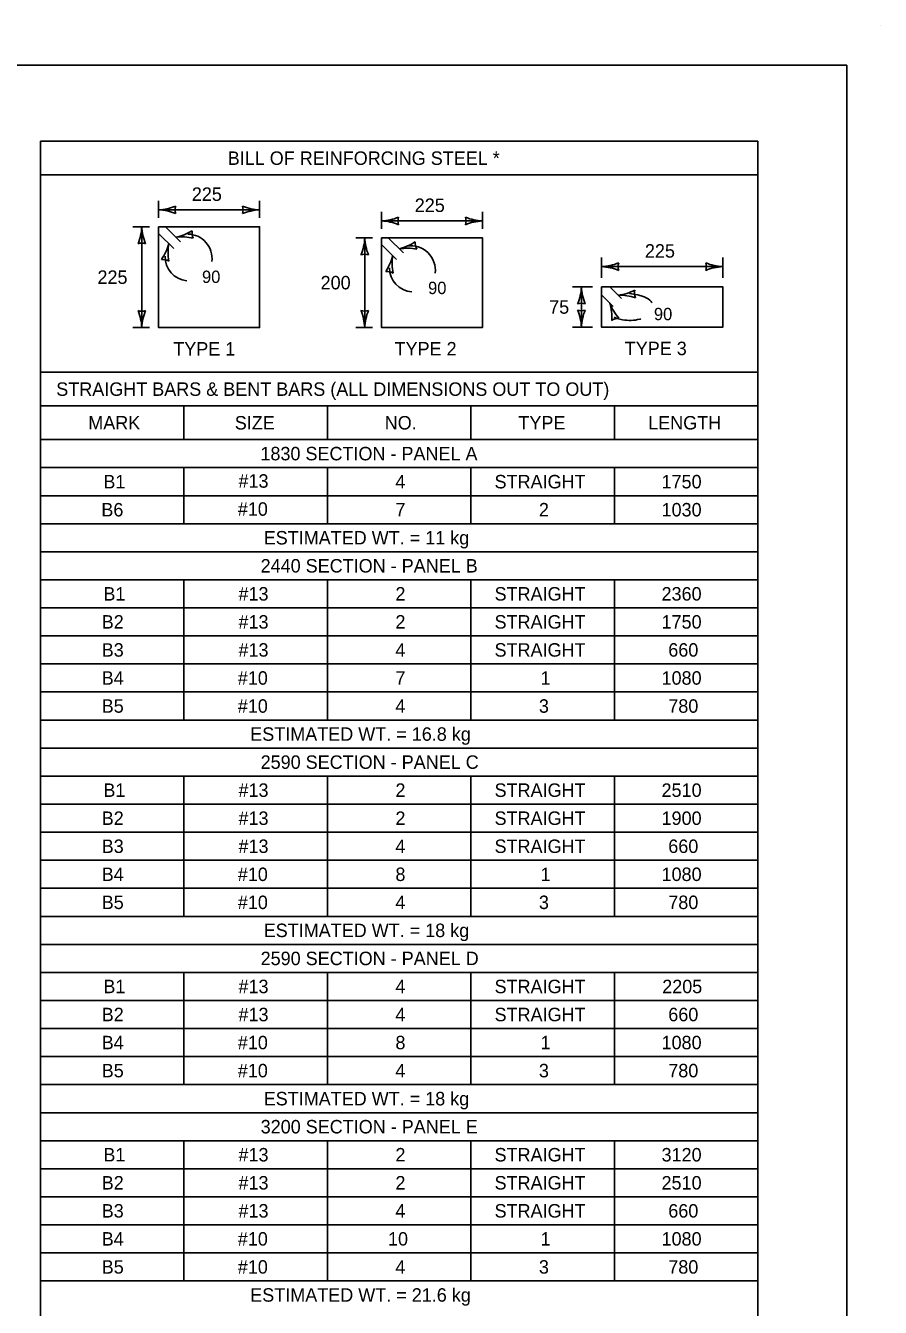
# Model space of a CAD drawing. Extents: x 49991.4 to 50021, y 49987.6 to 50011.4.
# Drawn here: x 50013.09 to 50016.9, y 49993.46 to 49999.18 of the extents above; entities that cross this region are included whole.
import ezdxf

# ---------------------------------------------------------------- set-up
doc = ezdxf.new("R2010")
doc.units = 0
for name, color, linetype in [('Level 1', 7, 'Continuous'), ('Level 2', 7, 'Continuous'), ('Level 3', 7, 'Continuous')]:
    doc.layers.add(name, color=color, linetype=linetype)

msp = doc.modelspace()

# ---------------------------------------------------------------- linework, layer by layer
at = {"layer": 'Level 1'}
for p, q in [((50016.9001, 49999.1756), (50016.9001, 49999.1756)), ((50013.713, 49998.2795), (50013.7802, 49998.2124)), ((50013.683, 49998.2495), (50013.7502, 49998.1824)), ((50014.7066, 49998.23), (50014.7738, 49998.1629)), ((50014.6766, 49998.2), (50014.7438, 49998.1329)), ((50015.6936, 49998.0114), (50015.7458, 49997.9592)), ((50015.6576, 49997.9754), (50015.7098, 49997.9232))]:
    msp.add_line(p, q, dxfattribs=at)
for points in [[(49999.3835, 49998.9992), (50016.7501, 49998.9992), (50016.7501, 49987.7988), (49999.3835, 49987.7988)], [(50013.683, 49998.2795), (50014.133, 49998.2795), (50014.133, 49997.8295), (50013.683, 49997.8295)], [(50014.6766, 49998.23), (50015.1266, 49998.23), (50015.1266, 49997.8299), (50014.6766, 49997.8299)], [(50015.6576, 49998.0114), (50016.1976, 49998.0114), (50016.1976, 49997.8314), (50015.6576, 49997.8314)]]:
    msp.add_lwpolyline(points, close=True, dxfattribs=at)
at = {"layer": 'Level 2'}
for p, q in [((50013.1565, 49998.6599), (50016.3545, 49998.6599)), ((50013.1565, 49991.0805), (50013.1565, 49998.6599)), ((50016.3545, 49991.0805), (50016.3545, 49998.6599)), ((50013.1565, 49998.5099), (50016.3545, 49998.5099)), ((50016.3545, 49997.6305), (50013.1565, 49997.6305)), ((50016.3545, 49997.4805), (50013.1565, 49997.4805)), ((50013.7961, 49997.3305), (50013.7961, 49997.4805)), ((50014.4357, 49997.3305), (50014.4357, 49997.4805)), ((50015.0753, 49997.3305), (50015.0753, 49997.4805)), ((50015.7149, 49997.3305), (50015.7149, 49997.4805)), ((50016.3545, 49997.3305), (50013.1565, 49997.3305)), ((50016.3545, 49997.2055), (50013.1565, 49997.2055)), ((50013.7961, 49996.9555), (50013.7961, 49997.2055)), ((50014.4357, 49996.9555), (50014.4357, 49997.2055)), ((50015.0753, 49996.9555), (50015.0753, 49997.2055)), ((50015.7149, 49996.9555), (50015.7149, 49997.2055)), ((50016.3545, 49997.0805), (50013.1565, 49997.0805)), ((50016.3545, 49996.9555), (50013.1565, 49996.9555)), ((50016.3545, 49996.8305), (50013.1565, 49996.8305)), ((50016.3545, 49996.7055), (50013.1565, 49996.7055)), ((50013.7961, 49996.0805), (50013.7961, 49996.7055)), ((50014.4357, 49996.0805), (50014.4357, 49996.7055)), ((50015.0753, 49996.0805), (50015.0753, 49996.7055)), ((50015.7149, 49996.0805), (50015.7149, 49996.7055)), ((50016.3545, 49996.5805), (50013.1565, 49996.5805)), ((50016.3545, 49996.4555), (50013.1565, 49996.4555)), ((50016.3545, 49996.3305), (50013.1565, 49996.3305)), ((50016.3545, 49996.2055), (50013.1565, 49996.2055)), ((50016.3545, 49996.0805), (50013.1565, 49996.0805)), ((50016.3545, 49995.9555), (50013.1565, 49995.9555)), ((50016.3545, 49995.8305), (50013.1565, 49995.8305)), ((50013.7961, 49995.2055), (50013.7961, 49995.8305)), ((50014.4357, 49995.2055), (50014.4357, 49995.8305)), ((50015.0753, 49995.2055), (50015.0753, 49995.8305)), ((50015.7149, 49995.2055), (50015.7149, 49995.8305)), ((50016.3545, 49995.7055), (50013.1565, 49995.7055)), ((50016.3545, 49995.5805), (50013.1565, 49995.5805)), ((50016.3545, 49995.4555), (50013.1565, 49995.4555)), ((50016.3545, 49995.3305), (50013.1565, 49995.3305)), ((50016.3545, 49995.2055), (50013.1565, 49995.2055)), ((50016.3545, 49995.0805), (50013.1565, 49995.0805)), ((50016.3545, 49994.9555), (50013.1565, 49994.9555)), ((50013.7961, 49994.4555), (50013.7961, 49994.9555)), ((50014.4357, 49994.4555), (50014.4357, 49994.9555)), ((50015.0753, 49994.4555), (50015.0753, 49994.9555)), ((50015.7149, 49994.4555), (50015.7149, 49994.9555)), ((50016.3545, 49994.8305), (50013.1565, 49994.8305)), ((50016.3545, 49994.7055), (50013.1565, 49994.7055)), ((50016.3545, 49994.5805), (50013.1565, 49994.5805)), ((50016.3545, 49994.4555), (50013.1565, 49994.4555)), ((50016.3545, 49994.3305), (50013.1565, 49994.3305)), ((50016.3545, 49994.2055), (50013.1565, 49994.2055)), ((50013.7961, 49993.5805), (50013.7961, 49994.2055)), ((50014.4357, 49993.5805), (50014.4357, 49994.2055)), ((50015.0753, 49993.5805), (50015.0753, 49994.2055)), ((50015.7149, 49993.5805), (50015.7149, 49994.2055)), ((50016.3545, 49994.0805), (50013.1565, 49994.0805)), ((50016.3545, 49993.9555), (50013.1565, 49993.9555)), ((50016.3545, 49993.8305), (50013.1565, 49993.8305)), ((50016.3545, 49993.7055), (50013.1565, 49993.7055)), ((50016.3545, 49993.5805), (50013.1565, 49993.5805))]:
    msp.add_line(p, q, dxfattribs=at)
at = {"layer": 'Level 3'}
for p, q in [((50013.683, 49998.3195), (50013.683, 49998.3945)), ((50014.133, 49998.3195), (50014.133, 49998.3945)), ((50013.683, 49998.3545), (50014.133, 49998.3545)), ((50014.6766, 49998.27), (50014.6766, 49998.345)), ((50015.1266, 49998.27), (50015.1266, 49998.345)), ((50013.643, 49998.2795), (50013.568, 49998.2795)), ((50013.608, 49997.8295), (50013.608, 49998.2795)), ((50014.6766, 49998.305), (50015.1266, 49998.305)), ((50014.6366, 49998.23), (50014.5616, 49998.23)), ((50014.6016, 49997.8299), (50014.6016, 49998.23)), ((50015.6576, 49998.0514), (50015.6576, 49998.1414)), ((50015.6576, 49998.1014), (50016.1976, 49998.1014)), ((50016.1976, 49998.0514), (50016.1976, 49998.1414)), ((50015.6176, 49998.0114), (50015.5275, 49998.0114)), ((50015.5675, 49997.8314), (50015.5675, 49998.0114)), ((50013.643, 49997.8295), (50013.568, 49997.8295)), ((50014.6366, 49997.8299), (50014.5616, 49997.8299)), ((50015.6176, 49997.8314), (50015.5275, 49997.8314))]:
    msp.add_line(p, q, dxfattribs=at)
for centre, radius, start, end in [((50013.6715, 49998.5872), 0.233, 272.8273, 292.0772), ((50013.6738, 49998.1324), 0.2223, 67.456, 87.6395), ((50013.8112, 49998.3545), 0.0548, 162.1388, 197.8612), ((50014.1422, 49998.5766), 0.2223, 247.456, 267.6395), ((50014.0048, 49998.3545), 0.0548, 342.1388, 17.8612), ((50014.1445, 49998.1218), 0.233, 92.8273, 112.0772), ((50013.3859, 49998.2887), 0.2223, 337.456, 357.6395), ((50013.8407, 49998.291), 0.233, 182.8273, 202.0772), ((50014.6651, 49998.5377), 0.233, 272.8273, 292.0772), ((50014.6674, 49998.0829), 0.2223, 67.456, 87.6395), ((50014.8048, 49998.305), 0.0548, 162.1388, 197.8612), ((50015.1358, 49998.5271), 0.2223, 247.456, 267.6395), ((50014.9984, 49998.305), 0.0548, 342.1388, 17.8612), ((50015.1381, 49998.0723), 0.233, 92.8273, 112.0772), ((50013.7131, 49998.461), 0.233, 281.5629, 300.8128), ((50013.7845, 49998.0118), 0.2223, 76.1916, 96.3752), ((50013.8131, 49998.138), 0.1081, 353.0327, 89.8236), ((50013.8866, 49998.2522), 0.0548, 170.8745, 206.5968), ((50014.3795, 49998.2392), 0.2223, 337.456, 357.6395), ((50014.8343, 49998.2415), 0.233, 182.8273, 202.0772), ((50014.6973, 49998.4059), 0.233, 284.6402, 303.8901), ((50014.8817, 49998.2067), 0.0548, 173.9517, 209.6741), ((50013.608, 49998.1513), 0.0548, 72.1388, 107.8612), ((50013.5139, 49998.2617), 0.2223, 324.7688, 344.9523), ((50013.9582, 49998.164), 0.233, 170.1401, 189.39), ((50014.6016, 49998.1018), 0.0548, 72.1388, 107.8612), ((50014.7927, 49997.9612), 0.2223, 79.2689, 99.4524), ((50014.8084, 49998.0856), 0.1081, 353.0327, 99.5284), ((50013.7005, 49998.0789), 0.0548, 59.4516, 95.174), ((50013.8199, 49998.1455), 0.1081, 178.4092, 263.8581), ((50014.5094, 49998.2007), 0.2223, 326.8049, 346.9884), ((50014.9569, 49998.1189), 0.233, 172.1762, 191.426), ((50015.6461, 49998.3341), 0.233, 272.8273, 292.0772), ((50015.6484, 49997.8793), 0.2223, 67.456, 87.6395), ((50015.7858, 49998.1014), 0.0548, 162.1388, 197.8612), ((50016.2068, 49998.3235), 0.2223, 247.456, 267.6395), ((50016.0694, 49998.1014), 0.0548, 342.1388, 17.8612), ((50016.2091, 49997.8687), 0.233, 92.8273, 112.0772), ((50014.7023, 49998.0246), 0.0548, 61.4877, 97.21), ((50014.8197, 49998.0967), 0.1081, 180.3082, 265.851), ((50015.3454, 49998.0206), 0.2223, 337.456, 357.6395), ((50015.8002, 49998.0229), 0.233, 182.8273, 202.0772), ((50015.7022, 49998.205), 0.233, 277.1537, 296.4036), ((50015.8591, 49997.9835), 0.0548, 166.4652, 202.1876), ((50015.5675, 49997.8832), 0.0548, 72.1388, 107.8612), ((50015.4807, 49997.8772), 0.2223, 355.8418, 16.0253), ((50015.9116, 49998.0229), 0.233, 201.2131, 220.4629), ((50015.7388, 49997.7516), 0.2223, 71.7824, 91.9659), ((50013.608, 49997.9577), 0.0548, 252.1388, 287.8612), ((50013.3753, 49997.818), 0.233, 2.8273, 22.0772), ((50013.8301, 49997.8203), 0.2223, 157.456, 177.6395), ((50014.6016, 49997.9581), 0.0548, 252.1388, 287.8612), ((50014.3689, 49997.8184), 0.233, 2.8273, 22.0772), ((50014.8237, 49997.8207), 0.2223, 157.456, 177.6395), ((50015.5675, 49997.9596), 0.0548, 252.1388, 287.8612), ((50015.3348, 49997.8199), 0.233, 2.8273, 22.0772), ((50015.7896, 49997.8222), 0.2223, 157.456, 177.6395), ((50015.7348, 49997.8169), 0.0548, 90.5246, 126.2469)]:
    msp.add_arc(centre, radius, start, end, dxfattribs=at)
for points in [[(50015.7818, 49997.9817), (50015.8184, 49997.9752), (50015.8382, 49997.9699), (50015.8719, 49997.9524), (50015.8833, 49997.9402)], [(50015.7133, 49997.8762), (50015.7267, 49997.8709), (50015.7511, 49997.8648), (50015.8275, 49997.8671), (50015.8324, 49997.8684)]]:
    msp.add_spline(points, degree=3, dxfattribs=at)

# ---------------------------------------------------------------- texts
at = {"layer": 'Level 2'}
for s, height, p in [('BILL OF REINFORCING STEEL *', 0.06, (50013.9909, 49998.5549)), ('225', 0.06, (50013.831, 49998.3945)), ('225', 0.06, (50014.8246, 49998.345)), ('225', 0.06, (50015.8506, 49998.1414)), ('225', 0.06, (50013.4104, 49998.0245)), ('90', 0.055, (50013.8764, 49998.0286)), ('200', 0.06, (50014.405, 49998)), ('90', 0.055, (50014.8841, 49997.979)), ('75', 0.06, (50015.4238, 49997.8914)), ('90', 0.055, (50015.8907, 49997.8626)), ('TYPE 1', 0.06, (50013.7483, 49997.705)), ('TYPE 2', 0.06, (50014.7347, 49997.7054)), ('TYPE 3', 0.06, (50015.7607, 49997.7069)), ('STRAIGHT BARS & BENT BARS (ALL DIMENSIONS OUT TO OUT)', 0.06, (50013.2267, 49997.5255)), ('MARK', 0.06, (50013.3693, 49997.3755)), ('SIZE', 0.06, (50014.0224, 49997.3755)), ('NO.', 0.06, (50014.6907, 49997.3755)), ('TYPE', 0.06, (50015.2867, 49997.3755)), ('LENGTH', 0.06, (50015.8651, 49997.3755)), ('1830 SECTION - PANEL A', 0.06, (50014.1367, 49997.238)), ('B1', 0.06, (50013.4367, 49997.113)), ('#13', 0.06, (50014.0389, 49997.116)), ('4', 0.06, (50014.7385, 49997.113)), ('STRAIGHT', 0.06, (50015.1804, 49997.113)), ('1750', 0.06, (50015.9248, 49997.113)), ('B6', 0.06, (50013.4277, 49996.988)), ('#10', 0.06, (50014.0359, 49996.991)), ('7', 0.06, (50014.7385, 49996.988)), ('2', 0.06, (50015.3781, 49996.988)), ('1030', 0.06, (50015.9248, 49996.988)), ('ESTIMATED WT. = 11 kg', 0.06, (50014.1514, 49996.863)), ('2440 SECTION - PANEL B', 0.06, (50014.1377, 49996.738)), ('B1', 0.06, (50013.4367, 49996.613)), ('#13', 0.06, (50014.0389, 49996.613)), ('2', 0.06, (50014.7385, 49996.613)), ('STRAIGHT', 0.06, (50015.1804, 49996.613)), ('2360', 0.06, (50015.9248, 49996.613)), ('B2', 0.06, (50013.4293, 49996.488)), ('#13', 0.06, (50014.0389, 49996.488)), ('2', 0.06, (50014.7385, 49996.488)), ('STRAIGHT', 0.06, (50015.1804, 49996.488)), ('1750', 0.06, (50015.9248, 49996.488)), ('B3', 0.06, (50013.4293, 49996.363)), ('#13', 0.06, (50014.0389, 49996.363)), ('4', 0.06, (50014.7385, 49996.363)), ('STRAIGHT', 0.06, (50015.1804, 49996.363)), ('660', 0.06, (50015.9548, 49996.363)), ('B4', 0.06, (50013.4293, 49996.238)), ('#10', 0.06, (50014.0359, 49996.238)), ('7', 0.06, (50014.7385, 49996.238)), ('1', 0.06, (50015.3855, 49996.238)), ('1080', 0.06, (50015.9248, 49996.238)), ('B5', 0.06, (50013.4293, 49996.113)), ('#10', 0.06, (50014.0359, 49996.113)), ('4', 0.06, (50014.7385, 49996.113)), ('3', 0.06, (50015.3781, 49996.113)), ('780', 0.06, (50015.9548, 49996.113)), ('ESTIMATED WT. = 16.8 kg', 0.06, (50014.0914, 49995.988)), ('2590 SECTION - PANEL C', 0.06, (50014.1377, 49995.863)), ('B1', 0.06, (50013.4367, 49995.738)), ('#13', 0.06, (50014.0389, 49995.738)), ('2', 0.06, (50014.7385, 49995.738)), ('STRAIGHT', 0.06, (50015.1804, 49995.738)), ('2510', 0.06, (50015.9248, 49995.738)), ('B2', 0.06, (50013.4293, 49995.613)), ('#13', 0.06, (50014.0389, 49995.613)), ('2', 0.06, (50014.7385, 49995.613)), ('STRAIGHT', 0.06, (50015.1804, 49995.613)), ('1900', 0.06, (50015.9248, 49995.613)), ('B3', 0.06, (50013.4293, 49995.488)), ('#13', 0.06, (50014.0389, 49995.488)), ('4', 0.06, (50014.7385, 49995.488)), ('STRAIGHT', 0.06, (50015.1804, 49995.488)), ('660', 0.06, (50015.9548, 49995.488)), ('B4', 0.06, (50013.4293, 49995.363)), ('#10', 0.06, (50014.0359, 49995.363)), ('8', 0.06, (50014.7385, 49995.363)), ('1', 0.06, (50015.3855, 49995.363)), ('1080', 0.06, (50015.9248, 49995.363)), ('B5', 0.06, (50013.4293, 49995.238)), ('#10', 0.06, (50014.0359, 49995.238)), ('4', 0.06, (50014.7385, 49995.238)), ('3', 0.06, (50015.3781, 49995.238)), ('780', 0.06, (50015.9548, 49995.238)), ('ESTIMATED WT. = 18 kg', 0.06, (50014.1514, 49995.113)), ('2590 SECTION - PANEL D', 0.06, (50014.1377, 49994.988)), ('B1', 0.06, (50013.4367, 49994.863)), ('#13', 0.06, (50014.0389, 49994.863)), ('4', 0.06, (50014.7385, 49994.863)), ('STRAIGHT', 0.06, (50015.1804, 49994.863)), ('2205', 0.06, (50015.9277, 49994.863)), ('B2', 0.06, (50013.4293, 49994.738)), ('#13', 0.06, (50014.0389, 49994.738)), ('4', 0.06, (50014.7385, 49994.738)), ('STRAIGHT', 0.06, (50015.1804, 49994.738)), ('660', 0.06, (50015.9548, 49994.738)), ('B4', 0.06, (50013.4293, 49994.613)), ('#10', 0.06, (50014.0359, 49994.613)), ('8', 0.06, (50014.7385, 49994.613)), ('1', 0.06, (50015.3855, 49994.613)), ('1080', 0.06, (50015.9248, 49994.613)), ('B5', 0.06, (50013.4293, 49994.488)), ('#10', 0.06, (50014.0359, 49994.488)), ('4', 0.06, (50014.7385, 49994.488)), ('3', 0.06, (50015.3781, 49994.488)), ('780', 0.06, (50015.9548, 49994.488)), ('ESTIMATED WT. = 18 kg', 0.06, (50014.1514, 49994.363)), ('3200 SECTION - PANEL E', 0.06, (50014.1379, 49994.238)), ('B1', 0.06, (50013.4367, 49994.113)), ('#13', 0.06, (50014.0389, 49994.113)), ('2', 0.06, (50014.7385, 49994.113)), ('STRAIGHT', 0.06, (50015.1804, 49994.113)), ('3120', 0.06, (50015.9248, 49994.113)), ('B2', 0.06, (50013.4293, 49993.988)), ('#13', 0.06, (50014.0389, 49993.988)), ('2', 0.06, (50014.7385, 49993.988)), ('STRAIGHT', 0.06, (50015.1804, 49993.988)), ('2510', 0.06, (50015.9248, 49993.988)), ('B3', 0.06, (50013.4293, 49993.863)), ('#13', 0.06, (50014.0389, 49993.863)), ('4', 0.06, (50014.7385, 49993.863)), ('STRAIGHT', 0.06, (50015.1804, 49993.863)), ('660', 0.06, (50015.9548, 49993.863)), ('B4', 0.06, (50013.4293, 49993.738)), ('#10', 0.06, (50014.0359, 49993.738)), ('10', 0.06, (50014.7055, 49993.738)), ('1', 0.06, (50015.3855, 49993.738)), ('1080', 0.06, (50015.9248, 49993.738)), ('B5', 0.06, (50013.4293, 49993.613)), ('#10', 0.06, (50014.0359, 49993.613)), ('4', 0.06, (50014.7385, 49993.613)), ('3', 0.06, (50015.3781, 49993.613)), ('780', 0.06, (50015.9548, 49993.613)), ('ESTIMATED WT. = 21.6 kg', 0.06, (50014.0914, 49993.488))]:
    msp.add_text(s, height=height, dxfattribs=at).set_placement(p)

doc.saveas('drawing.dxf')
